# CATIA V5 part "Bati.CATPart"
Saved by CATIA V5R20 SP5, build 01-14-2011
Part number: Bâti
Bounding box of the stored display mesh (mm): x -40.694 to 107.307, y -54.347 to 125.654, z -5 to 8
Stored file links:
  D:\thinkmotion-MPB\Dropbox\IAO_2011\MMS_GR3\IAO_2011_1523_mkessler\mkessler\mkessler_IAO\mkessler_INIT\Bati.CATPart
  C:\Users\MARLENE\Documents\IFMA\S3\IAO\Copie de CAO\Assemblage_final.CATProduct
  D:\thinkmotion-MPB\Dropbox\IAO_2011\MMS_GR3\IAO_2011_1523_mkessler\mkessler\mkessler_IAO\mkessler_INIT\Squelette_bati.CATPart
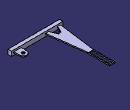
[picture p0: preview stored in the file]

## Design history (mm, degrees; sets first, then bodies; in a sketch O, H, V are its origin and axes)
External parameters (linked from other documents)
  External.Largeur_ext_glissiere_2 = 15 mm
  External.Longueur_ext_glissiere_2 = 64 mm
  External.Largeur_int_glissiere_2 = 10 mm
  `External.Longueur_int_glissière_2` = 58 mm
Set1
  Plane1: linked copy from another document
  Line1 to Line4: linked copy from another document
  Point1: linked copy from another document
  Point2: linked copy from another document
Body1 (main body)
  Sketch1 on Plane1, origin (0, 0, 0), H (1, 0, 0), V (0, 1, 0)
    line L1 (-19.9355, 125.654) -> (-4.9355, 125.654)
    line L2 (-4.9355, 125.654) -> (-4.9355, 61.654)
    line L3 (-19.9355, 61.654) -> (-19.9355, 125.654)
    point P3 (-4.9355, 61.654)
    line L4 (-17.4355, 122.654) -> (-7.4355, 122.654)
    line L5 (-7.4355, 122.654) -> (-7.4355, 64.654)
    line L6 (-7.4355, 64.654) -> (-17.4355, 64.654)
    line L7 (-17.4355, 64.654) -> (-17.4355, 122.654)
    construction line L8 (-12.4355, 82.8207) -> (-12.4355, -53.291)
    line L9 (-19.9355, 61.654) -> (-33.6933, -44.346)
    line L10 (-33.6933, -44.346) -> (-25.5591, -44.346)
    point P13 (-4.9355, 61.654)
    line L11 (-4.9355, 61.654) -> (8.8222, -44.346)
    line L12 (8.8222, -44.346) -> (0.688, -44.346)
    circle A1 centre (-12.4355, -26.346) radius 2
    arc A2 centre (-12.4355, -26.346) radius 4 from (-16.0383, -24.6082) to (-8.8328, -24.6082) ccw
    line L13 (-25.5591, -44.346) -> (-16.0383, -24.6082)
    line L14 (0.688, -44.346) -> (-8.8328, -24.6082)
    line L15 (78.8724, -44.3443) -> (101.1455, -44.346)
    circle A3 centre (89.5645, -28.346) radius 4.5
    arc A4 centre (89.5645, -28.346) radius 9.9174 from (99.3933, -27.0239) to (79.6923, -27.4004) ccw
    line L16 (79.6923, -27.4004) -> (78.8724, -44.3443)
    line L17 (99.3933, -27.0239) -> (101.1455, -44.346)
    length L1 = 15 {= External.Largeur_ext_glissiere_2}
    length L3 = 64 {= External.Longueur_ext_glissiere_2}
    length L4 = 10 {= External.Largeur_int_glissiere_2}
    length L7 = 58 {= `External.Longueur_int_glissière_2`}
    radius A1 = 2
    radius A2 = 4
    radius A3 = 4.5
    coincidence: P3 P13
  Pad1: profile Sketch1, direction (0, 0, 1), length 3
  Sketch2 on face of Pad1 from Sketch1.L15, origin (-0.0034, -44.3383, 0), H (1, -0.0001, 0), V (0, 0, 1)
    line L1 (-40.6899, 8) -> (107.3101, 8)
    line L2 (107.3101, 8) -> (107.3101, -5)
    line L3 (107.3101, -5) -> (-40.6899, -5)
    line L4 (-40.6899, -5) -> (-40.6899, 8)
    reference projected line E1 (-33.6899, 0) -> (-33.6899, 3) from edge [face of Pad1 from Sketch1.L10 | face of Pad1 from Sketch1.L9]
    reference projected line E2 (-33.6899, 3) -> (-25.5557, 3) from edge [face of Pad1 from Sketch1.L10 | end face of Pad1]
    length L1 = 148
    distance E1 L4 = 7
    distance E2 L1 = 5
    distance L1 L3 = 13
  Pad2: profile Sketch2, direction (-0.0001, -1, 0), length 10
